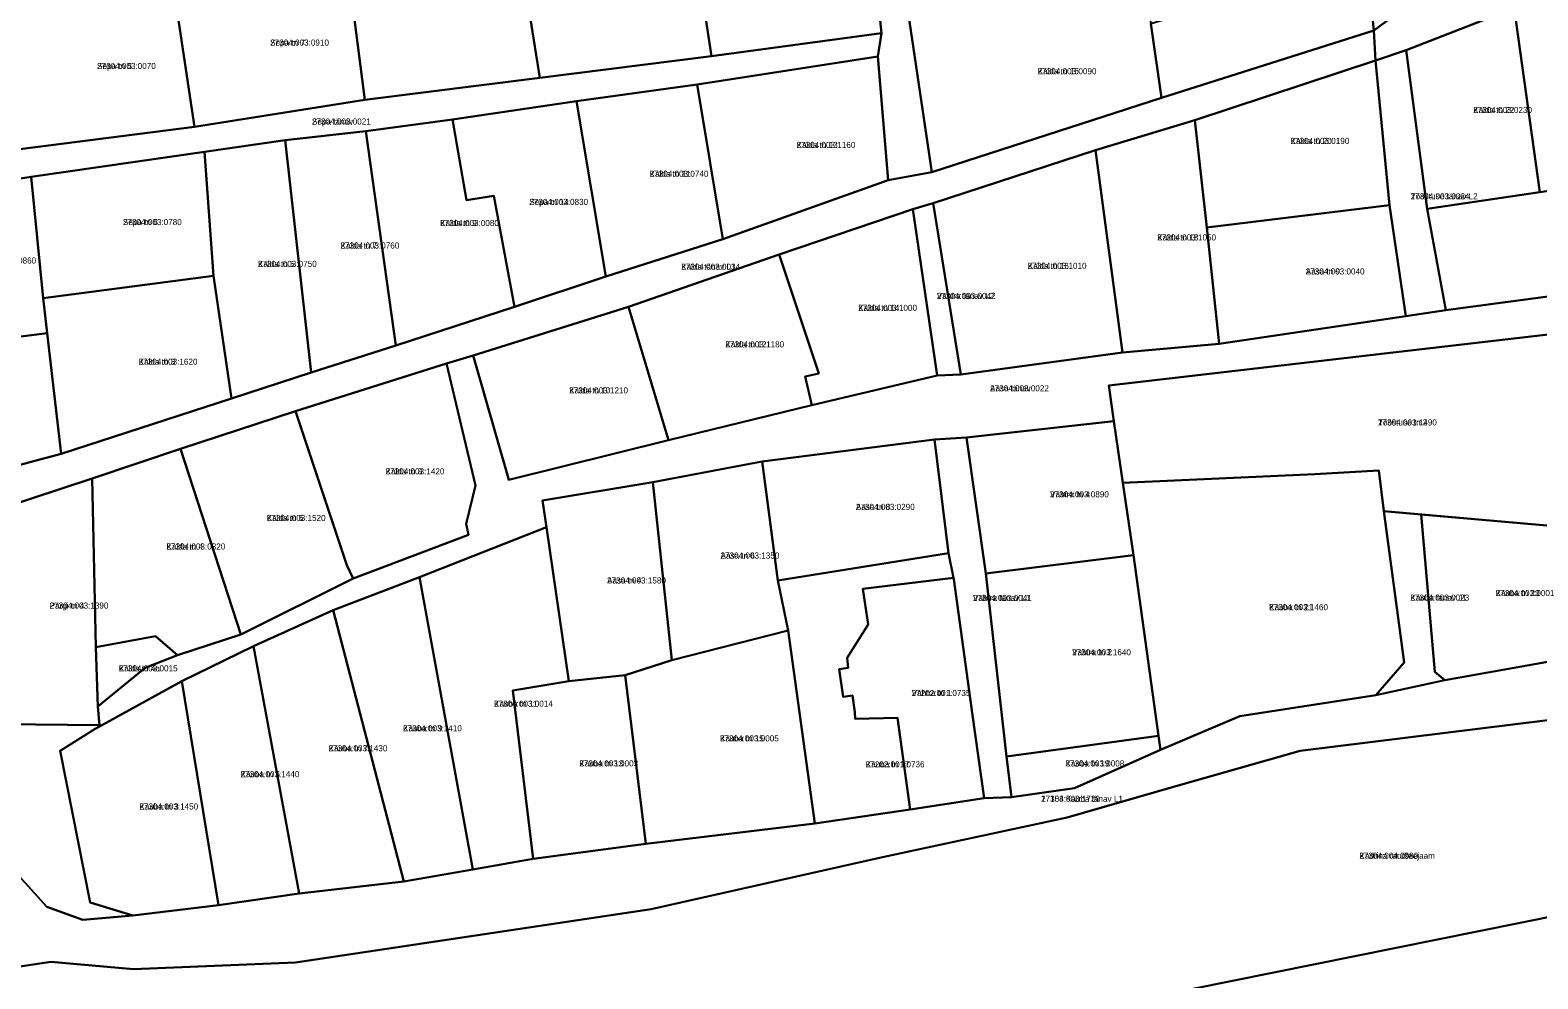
# Model space of a CAD drawing. Extents: x 603789 to 628102, y 6569852 to 6597259.
# Drawn here: x 621695.7 to 622067.3, y 6579689.4 to 6579923.2 of the extents above; entities that cross this region are included whole.
import ezdxf

# ---------------------------------------------------------------- set-up
doc = ezdxf.new("R2010")
doc.units = 0
for name, color, linetype in [('L_AADRESS', 7, 'Continuous'), ('PIIR', 7, 'Continuous'), ('TUNNUS', 7, 'Continuous')]:
    doc.layers.add(name, color=color, linetype=linetype)

msp = doc.modelspace()

# ---------------------------------------------------------------- linework, layer by layer
at = {"layer": 'PIIR'}
for points in [[(622013.59, 6580025.51), (622021.06, 6580026.66), (622024.91, 6579994.79), (622029.25, 6579963.89), (622034.01, 6579928.32), (622026.85, 6579923.06), (622023.87, 6579953.51), (622022.41, 6579961.69), (622019.32, 6579983.46)], [(621894.05, 6580008.11), (621900.49, 6580009.99), (621905.92, 6579969.21), (621909.28, 6579947.4), (621912.07, 6579927.5), (621917.92, 6579888.13), (621907.16, 6579886.23), (621904.64, 6579916.63), (621905.56, 6579922.4), (621901.9, 6579956.82)], [(621858.43, 6579950.69), (621880.3, 6579953.76), (621901.9, 6579956.82), (621905.56, 6579922.4), (621863.61, 6579916.77)], [(621971.91, 6579924.77), (622008.89, 6579935.8), (622006.73, 6579951.26), (622023.87, 6579953.51), (622026.85, 6579923.06), (621974.57, 6579906.47)], [(621816.55, 6579941.42), (621837.76, 6579946.06), (621858.43, 6579950.69), (621863.61, 6579916.77), (621821.33, 6579911.38)], [(621731.11, 6579933.34), (621752.35, 6579936.36), (621773.85, 6579939.38), (621774.4, 6579935.37), (621778.13, 6579906.01), (621736.16, 6579899.33)], [(621774.4, 6579935.37), (621796, 6579938.49), (621816.55, 6579941.42), (621821.33, 6579911.38), (621778.13, 6579906.01)], [(621917.92, 6579888.13), (621912.07, 6579927.5), (621970.21, 6579936.48), (621971.91, 6579924.77), (621974.57, 6579906.47)], [(622061.48, 6579928.59), (622084.25, 6579937.86), (622091.14, 6579889.62), (622091.61, 6579886.88), (622067.85, 6579883.26)], [(621693.12, 6579893.83), (621688.07, 6579928.13), (621711.3, 6579930.94), (621731.11, 6579933.34), (621736.16, 6579899.33)], [(622034.9, 6579918.24), (622061.48, 6579928.59), (622067.85, 6579883.26), (622040.03, 6579879.14)], [(621623.98, 6579885.51), (621649.58, 6579888.18), (621693.12, 6579893.83), (621736.16, 6579899.33), (621778.13, 6579906.01), (621821.33, 6579911.38), (621863.61, 6579916.77), (621905.56, 6579922.4), (621904.64, 6579916.63), (621860.06, 6579909.79), (621830.34, 6579905.7), (621799.8, 6579901.17), (621778.38, 6579898.26), (621758.51, 6579896.08), (621738.64, 6579893.17), (621695.91, 6579887.03), (621665.41, 6579882.35), (621628.81, 6579877.41)], [(621860.06, 6579909.79), (621904.64, 6579916.63), (621907.16, 6579886.23), (621866.37, 6579871.63)], [(621982.74, 6579900.96), (622027.32, 6579915.69), (622030.76, 6579880.06), (621985.71, 6579874.56)], [(622027.32, 6579915.69), (622034.9, 6579918.24), (622040.03, 6579879.14), (622044.62, 6579854.13), (622034.74, 6579852.7), (622030.76, 6579880.06)], [(621830.34, 6579905.7), (621860.06, 6579909.79), (621866.37, 6579871.63), (621837.6, 6579862.43)], [(621809.97, 6579882.29), (621803.25, 6579881.25), (621799.8, 6579901.17), (621830.34, 6579905.7), (621837.6, 6579862.43), (621815.04, 6579854.98)], [(621785.81, 6579845.48), (621778.38, 6579898.26), (621799.8, 6579901.17), (621803.25, 6579881.25), (621809.97, 6579882.29), (621815.04, 6579854.98)], [(621958.24, 6579893.61), (621982.74, 6579900.96), (621985.71, 6579874.56), (621988.76, 6579845.84), (621964.89, 6579843.7)], [(621758.51, 6579896.08), (621778.38, 6579898.26), (621785.81, 6579845.48), (621764.93, 6579838.79)], [(621740.87, 6579862.65), (621738.64, 6579893.17), (621758.51, 6579896.08), (621764.93, 6579838.79), (621745.26, 6579832.42)], [(621918.25, 6579880.49), (621958.24, 6579893.61), (621964.89, 6579843.7), (621925.07, 6579838.28)], [(621695.91, 6579887.03), (621738.64, 6579893.17), (621740.87, 6579862.65), (621698.86, 6579857.08)], [(621665.41, 6579882.35), (621695.91, 6579887.03), (621698.86, 6579857.08), (621699.85, 6579848.48), (621669.48, 6579844.6)], [(622091.61, 6579886.88), (622095.55, 6579860.95), (622044.62, 6579854.13), (622040.03, 6579879.14), (622067.85, 6579883.26)], [(621880.26, 6579867.88), (621913.23, 6579879.08), (621919.28, 6579838.04), (621888.33, 6579830.72), (621886.7, 6579837.78), (621890.07, 6579838.51)], [(621913.23, 6579879.08), (621918.25, 6579880.49), (621925.07, 6579838.28), (621919.28, 6579838.04)], [(622030.76, 6579880.06), (622034.74, 6579852.7), (621988.76, 6579845.84), (621985.71, 6579874.56)], [(621843.17, 6579854.95), (621880.26, 6579867.88), (621890.07, 6579838.51), (621886.7, 6579837.78), (621888.33, 6579830.72), (621853.01, 6579822.08)], [(621699.85, 6579848.48), (621698.86, 6579857.08), (621740.87, 6579862.65), (621745.26, 6579832.42), (621703.27, 6579818.76)], [(621804.82, 6579842.98), (621843.17, 6579854.95), (621853.01, 6579822.08), (621813.63, 6579812.31)], [(621965.04, 6579811.57), (621962.83, 6579826.78), (621961.56, 6579835.58), (622090.44, 6579850.56), (622093.61, 6579818.2), (622071.41, 6579800.89), (622029.32, 6579804.59), (622028.08, 6579814.64), (622012.35, 6579813.75)], [(621645.12, 6579841.22), (621669.48, 6579844.6), (621699.85, 6579848.48), (621703.27, 6579818.76), (621661.69, 6579807.64)], [(621798.32, 6579841.02), (621805.46, 6579810.9), (621803.15, 6579801.48), (621803.67, 6579798.82), (621775.25, 6579788.02), (621773.7, 6579791.31), (621761.1, 6579829.29)], [(621732.71, 6579820.01), (621761.1, 6579829.29), (621773.7, 6579791.31), (621775.25, 6579788.02), (621747.59, 6579774.25)], [(621926.47, 6579822.81), (621962.83, 6579826.78), (621965.04, 6579811.57), (621967.67, 6579793.73), (621931.23, 6579789.26)], [(621918.57, 6579822.31), (621926.47, 6579822.81), (621931.23, 6579789.26), (621936.34, 6579744.11), (621937.57, 6579734.12), (621930.8, 6579733.84), (621927.94, 6579754.35), (621923.37, 6579787.89), (621923.3, 6579788.22), (621922.06, 6579794.25)], [(621732.71, 6579820.01), (621747.59, 6579774.25), (621731.96, 6579769.14), (621726.59, 6579773.77), (621711.82, 6579771.11), (621710.9, 6579812.66)], [(621876.14, 6579816.83), (621918.57, 6579822.31), (621922.06, 6579794.25), (621879.97, 6579787.53)], [(621849.18, 6579811.75), (621876.14, 6579816.83), (621879.97, 6579787.53), (621882.49, 6579775.24), (621853.8, 6579767.88)], [(621688.15, 6579805.16), (621710.9, 6579812.66), (621711.82, 6579771.11), (621712.3, 6579756.5), (621712.74, 6579751.84), (621689.06, 6579752.14)], [(621821.97, 6579807.26), (621849.18, 6579811.75), (621853.8, 6579767.88), (621842.3, 6579764.16), (621828.41, 6579762.69), (621822.92, 6579800.69)], [(621965.04, 6579811.57), (622012.35, 6579813.75), (622028.08, 6579814.64), (622029.32, 6579804.59), (622034.4, 6579767.28), (622027.39, 6579759.24), (621993.82, 6579754.06), (621974.27, 6579745.78), (621973.79, 6579749.25), (621967.67, 6579793.73)], [(622029.32, 6579804.59), (622038.53, 6579803.78), (622041.92, 6579764.98), (622044.4, 6579762.97), (622027.39, 6579759.24), (622034.4, 6579767.28)], [(621822.92, 6579800.69), (621828.41, 6579762.69), (621814.66, 6579760.38), (621819.63, 6579718.92), (621804.78, 6579716.32), (621791.6, 6579788.36)], [(622071.41, 6579800.89), (622075.29, 6579768.47), (622044.4, 6579762.97), (622041.92, 6579764.98), (622038.53, 6579803.78)], [(621912.6, 6579731.1), (621889.1, 6579727.61), (621882.49, 6579775.24), (621879.97, 6579787.53), (621922.06, 6579794.25), (621923.3, 6579788.22), (621900.88, 6579785.47), (621902.22, 6579776.7), (621897.02, 6579768.46), (621897.28, 6579765.98), (621895.11, 6579765.69), (621896.08, 6579758.87), (621898.35, 6579759.2), (621898.94, 6579755.08), (621899.07, 6579753.44), (621909.45, 6579753.67)], [(621931.23, 6579789.26), (621967.67, 6579793.73), (621973.79, 6579749.25), (621936.34, 6579744.11)], [(621787.73, 6579713.31), (621770.37, 6579780.19), (621791.6, 6579788.36), (621804.78, 6579716.32)], [(621930.8, 6579733.84), (621912.6, 6579731.1), (621909.45, 6579753.67), (621899.07, 6579753.44), (621898.94, 6579755.08), (621898.35, 6579759.2), (621896.08, 6579758.87), (621895.11, 6579765.69), (621897.28, 6579765.98), (621897.02, 6579768.46), (621902.22, 6579776.7), (621900.88, 6579785.47), (621923.3, 6579788.22), (621923.37, 6579787.89), (621927.94, 6579754.35)], [(621750.69, 6579771.33), (621770.37, 6579780.19), (621787.73, 6579713.31), (621761.98, 6579710.4)], [(621842.3, 6579764.16), (621853.8, 6579767.88), (621882.49, 6579775.24), (621889.1, 6579727.61), (621847.41, 6579722.62)], [(621711.82, 6579771.11), (621726.59, 6579773.77), (621731.96, 6579769.14), (621724.04, 6579765.98), (621712.3, 6579756.5)], [(621733.06, 6579762.74), (621750.69, 6579771.33), (621761.98, 6579710.4), (621742.11, 6579707.53)], [(621819.63, 6579718.92), (621814.66, 6579760.38), (621828.41, 6579762.69), (621842.3, 6579764.16), (621847.41, 6579722.62)], [(621710.43, 6579708.13), (621703.05, 6579745.54), (621711.64, 6579750.95), (621712.77, 6579751.57), (621733.06, 6579762.74), (621742.11, 6579707.53), (621720.95, 6579705)], [(621936.34, 6579744.11), (621973.79, 6579749.25), (621974.27, 6579745.78), (621953.1, 6579736.31), (621937.57, 6579734.12)], [(622133.87, 6579717.48), (622145.32, 6579671.81), (621710.27, 6579616.37), (621708.39, 6579631.66)]]:
    msp.add_lwpolyline(points, close=True, dxfattribs=at)
for points in [[(622084.25, 6579937.86), (622061.48, 6579928.59), (622034.9, 6579918.24), (622027.32, 6579915.69), (622026.85, 6579923.06), (622034.01, 6579928.32), (622074.15, 6579942.81)], [(621661.69, 6579807.64), (621703.27, 6579818.76), (621745.26, 6579832.42), (621764.93, 6579838.79), (621785.81, 6579845.48), (621815.04, 6579854.98), (621837.6, 6579862.43), (621866.37, 6579871.63), (621907.16, 6579886.23), (621917.92, 6579888.13), (621974.57, 6579906.47), (622026.85, 6579923.06), (622027.32, 6579915.69), (621982.74, 6579900.96), (621958.24, 6579893.61), (621918.25, 6579880.49), (621913.23, 6579879.08), (621880.26, 6579867.88), (621843.17, 6579854.95), (621804.82, 6579842.98), (621798.32, 6579841.02), (621761.1, 6579829.29), (621732.71, 6579820.01), (621710.9, 6579812.66), (621688.15, 6579805.16)], [(622090.44, 6579850.56), (621961.56, 6579835.58), (621962.83, 6579826.78), (621926.47, 6579822.81), (621918.57, 6579822.31), (621876.14, 6579816.83), (621849.18, 6579811.75), (621821.97, 6579807.26), (621822.92, 6579800.69), (621791.6, 6579788.36), (621770.37, 6579780.19), (621750.69, 6579771.33), (621733.06, 6579762.74), (621712.77, 6579751.57), (621712.74, 6579751.84), (621712.3, 6579756.5), (621724.04, 6579765.98), (621731.96, 6579769.14), (621747.59, 6579774.25), (621775.25, 6579788.02), (621803.67, 6579798.82), (621803.15, 6579801.48), (621805.46, 6579810.9), (621798.32, 6579841.02), (621804.82, 6579842.98), (621813.63, 6579812.31), (621853.01, 6579822.08), (621888.33, 6579830.72), (621919.28, 6579838.04), (621925.07, 6579838.28), (621964.89, 6579843.7), (621988.76, 6579845.84), (622034.74, 6579852.7), (622044.62, 6579854.13), (622095.55, 6579860.95)], [(621409.97, 6579666.73), (621622.72, 6579719.42), (621662.81, 6579718.6), (621680.99, 6579702.57), (621686.54, 6579691.4), (621700.76, 6579693.54), (621721.11, 6579691.73), (621761.07, 6579693.39), (621848.7, 6579706.53), (621905.77, 6579719.38), (621951.29, 6579729.12), (621977.5, 6579736.71), (622008.7, 6579745.52), (622122.2, 6579759.63), (622121.09, 6579766.04), (622183.59, 6579775.25), (622224.39, 6579787.62), (622257.04, 6579792.02), (622257.76, 6579785.82), (622372.24, 6579800.71), (622548.52, 6579823.88), (622546.93, 6579836.13), (622636.07, 6579857.88)], [(622604.54, 6579779.17), (622546.88, 6579771.27), (622490.85, 6579763.08), (622450.48, 6579758.04), (622412.21, 6579753.29), (622417.7, 6579706.5), (622351.14, 6579697.56), (622346.87, 6579713.5), (622342.78, 6579760.66), (622305.59, 6579755.32), (622262.25, 6579749.45), (622202.25, 6579741.32), (622204.15, 6579727.31), (622164.38, 6579722.17), (622156.45, 6579721.15), (622133.87, 6579717.48), (621708.39, 6579631.66)], [(621691.41, 6579716.38), (621699.74, 6579707.13), (621708.64, 6579703.9), (621720.95, 6579705), (621742.11, 6579707.53), (621761.98, 6579710.4), (621787.73, 6579713.31), (621804.78, 6579716.32), (621819.63, 6579718.92), (621847.41, 6579722.62), (621889.1, 6579727.61), (621912.6, 6579731.1), (621930.8, 6579733.84), (621937.57, 6579734.12), (621953.1, 6579736.31), (621974.27, 6579745.78), (621993.82, 6579754.06), (622027.39, 6579759.24), (622044.4, 6579762.97), (622075.29, 6579768.47)], [(622122.2, 6579759.63), (622008.7, 6579745.52), (621977.5, 6579736.71), (621951.29, 6579729.12), (621905.77, 6579719.38), (621848.7, 6579706.53), (621761.07, 6579693.39), (621721.11, 6579691.73), (621700.76, 6579693.54), (621686.54, 6579691.4)], [(621689.06, 6579752.14), (621712.74, 6579751.84), (621712.77, 6579751.57), (621711.64, 6579750.95), (621703.05, 6579745.54), (621710.43, 6579708.13), (621720.95, 6579705), (621708.64, 6579703.9), (621699.74, 6579707.13), (621691.41, 6579716.38)]]:
    msp.add_lwpolyline(points, dxfattribs=at)

# ---------------------------------------------------------------- texts
at = {"layer": 'L_AADRESS'}
for s, p in [('Sepa tn 7', (621754.81, 6579919.35)), ('Sepa tn 5', (621712.13, 6579913.58)), ('Kalda tn 15', (621944.02, 6579912.3)), ('Sepa tänav', (621765.13, 6579899.9)), ('Kalda tn 22', (622051.38, 6579902.74)), ('Kalda tn 13', (621884.58, 6579894.13)), ('Kalda tn 20', (622006.35, 6579895.12)), ('Kalda tn 11', (621848.36, 6579887.02)), ('Tööstuse tänav L2', (622035.97, 6579881.48)), ('Sepa tn 14', (621818.7, 6579880.08)), ('Sepa tn 6', (621718.52, 6579875.12)), ('Kalda tn 9', (621796.71, 6579874.89)), ('Kalda tn 18', (621973.5, 6579871.33)), ('Kalda tn 7', (621772.16, 6579869.34)), ('Kalda tn 5', (621751.79, 6579864.81)), ('Kalda tänav L1', (621856.15, 6579864.11)), ('Kalda tn 16', (621941.57, 6579864.33)), ('Aasa tn 9', (622010.1, 6579862.95)), ('Vahtra tänav L2', (621919.15, 6579856.92)), ('Kalda tn 14', (621899.77, 6579853.97)), ('Kalda tn 12', (621867.03, 6579844.98)), ('Kalda tn 3', (621722.4, 6579840.71)), ('Kalda tn 10', (621828.53, 6579833.63)), ('Aasa tänav', (621932.29, 6579834.15)), ('Tööstuse tn 2', (622027.93, 6579825.73)), ('Kalda tn 8', (621783.28, 6579813.68)), ('Vahtra tn 4', (621947.07, 6579808.02)), ('Aasa tn 8', (621899.21, 6579804.92)), ('Kalda tn 6', (621753.98, 6579802.2)), ('Kalda tn 4', (621729.25, 6579795.16)), ('Aasa tn 6', (621865.84, 6579792.93)), ('Aasa tn 4', (621837.88, 6579786.79)), ('Pargi tn 4', (621700.45, 6579780.6)), ('Vahtra tänav L1', (621928.07, 6579782.48)), ('Kauba tn 21', (622001.08, 6579780.21)), ('Kauba tänav J1', (622035.89, 6579782.56)), ('Kauba tn 23', (622056.91, 6579783.68)), ('Vahtra tn 2', (621952.51, 6579769.1)), ('Kalda tn 4a', (621717.5, 6579765.13)), ('Vahtra tn 1', (621912.95, 6579759.05)), ('Kauba tn 11', (621810, 6579756.42)), ('Kauba tn 9', (621787.57, 6579750.36)), ('Kauba tn 15', (621865.7, 6579747.87)), ('Kauba tn 7', (621769.21, 6579745.44)), ('Kauba tn 13', (621831.03, 6579741.7)), ('Kauba tn 17', (621901.63, 6579741.48)), ('Kauba tn 19', (621950.88, 6579741.69)), ('Kauba tn 5', (621747.52, 6579739.05)), ('17153 Kauba tänav L1', (621944.85, 6579732.98)), ('Kauba tn 3', (621722.58, 6579731.08)), ('Kadrina raudteejaam', (622023.33, 6579718.94))]:
    msp.add_text(s, height=1.5, dxfattribs=at).set_placement(p)
at = {"layer": 'TUNNUS'}
for s, p in [('27304:003:0910', (621754.81, 6579919.35)), ('27304:003:0070', (621712.13, 6579913.58)), ('27304:003:0090', (621944.02, 6579912.3)), ('27304:003:0021', (621765.13, 6579899.9)), ('27304:003:0230', (622051.38, 6579902.74)), ('27304:003:1160', (621884.58, 6579894.13)), ('27304:003:0190', (622006.35, 6579895.12)), ('27304:003:0740', (621848.36, 6579887.02)), ('27304:003:0024', (622035.97, 6579881.48)), ('27304:003:0830', (621818.7, 6579880.08)), ('27304:003:0780', (621718.52, 6579875.12)), ('27304:003:0080', (621796.71, 6579874.89)), ('27304:003:1050', (621973.5, 6579871.33)), ('27304:003:0760', (621772.16, 6579869.34)), ('27304:003:0860', (621682.63, 6579865.64)), ('27304:003:0750', (621751.79, 6579864.81)), ('27304:003:0034', (621856.15, 6579864.11)), ('27304:003:1010', (621941.57, 6579864.33)), ('27304:003:0040', (622010.1, 6579862.95)), ('27304:003:0042', (621919.15, 6579856.92)), ('27304:003:1000', (621899.77, 6579853.97)), ('27304:003:1180', (621867.03, 6579844.98)), ('27304:003:1620', (621722.4, 6579840.71)), ('27304:003:1210', (621828.53, 6579833.63)), ('27304:003:0022', (621932.29, 6579834.15)), ('27304:003:1490', (622027.93, 6579825.73)), ('27304:003:1420', (621783.28, 6579813.68)), ('27304:003:0890', (621947.07, 6579808.02)), ('27304:003:0290', (621899.21, 6579804.92)), ('27304:003:1520', (621753.98, 6579802.2)), ('27304:003:0320', (621729.25, 6579795.16)), ('27304:003:1350', (621865.84, 6579792.93)), ('27304:003:1580', (621837.88, 6579786.79)), ('27304:003:1390', (621700.45, 6579780.6)), ('27304:003:0041', (621928.07, 6579782.48)), ('27304:003:0023', (622035.89, 6579782.56)), ('27304:003:0001', (622056.91, 6579783.68)), ('27304:003:1460', (622001.08, 6579780.21)), ('27304:003:1640', (621952.51, 6579769.1)), ('27304:003:0015', (621717.5, 6579765.13)), ('27202:001:0735', (621912.95, 6579759.05)), ('27304:003:0014', (621810, 6579756.42)), ('27304:003:1410', (621787.57, 6579750.36)), ('27304:003:0005', (621865.7, 6579747.87)), ('27304:003:1430', (621769.21, 6579745.44)), ('27304:003:0003', (621831.03, 6579741.7)), ('27202:001:0736', (621901.63, 6579741.48)), ('27304:003:0008', (621950.88, 6579741.69)), ('27304:003:1440', (621747.52, 6579739.05)), ('27304:003:1720', (621944.85, 6579732.98)), ('27304:003:1450', (621722.58, 6579731.08)), ('27304:004:0980', (622023.33, 6579718.94))]:
    msp.add_text(s, height=1.5, dxfattribs=at).set_placement(p)

doc.saveas('drawing.dxf')
